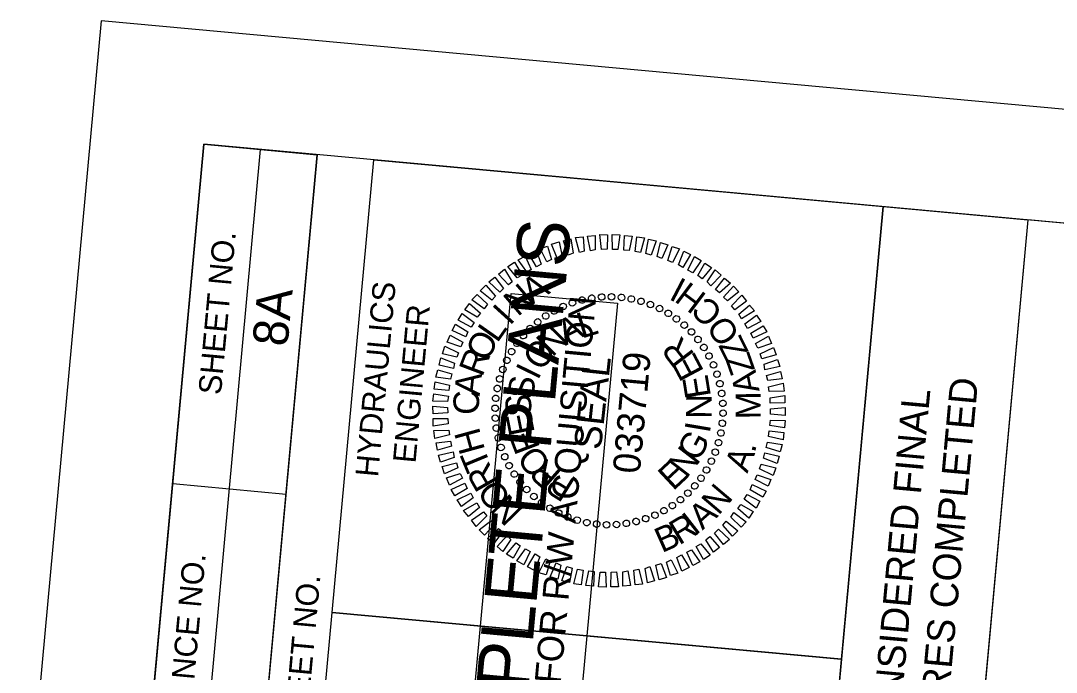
# Model space of a CAD drawing. Extents: x 2012234 to 2013485, y 445892 to 447846.
# Drawn here: x 2012372.3 to 2012600.1, y 447702.6 to 447846 of the extents above; entities that cross this region are included whole.
import ezdxf

# ---------------------------------------------------------------- set-up
doc = ezdxf.new("R2010")
doc.units = 0
for name, color, linetype in [('Sheet Clip Boundary CELL', 7, 'Continuous'), ('Sheet Data Field CELL', 7, 'Continuous'), ('Sheet Plan And Profile CELL', 7, 'Continuous'), ('Sheet Plot Border Outside CELL', 7, 'Continuous'), ('Sheet Professional Seal CELL', 7, 'Continuous'), ('Sheet Profile Grid Minor CELL', 7, 'Continuous'), ('Sheet Sticker Exception Certification CELL', 7, 'Continuous'), ('Sheet Sticker Incomplete CELL', 7, 'Continuous')]:
    doc.layers.add(name, color=color, linetype=linetype)

msp = doc.modelspace()

# ---------------------------------------------------------------- linework, layer by layer
at = {"layer": 'Sheet Clip Boundary CELL'}
msp.add_lwpolyline([(2012286.31, 446445.78), (2012511.43, 446429.21), (2012750.66, 446410.08), (2013333.05, 446362.08), (2013458.14, 447722.64), (2012593.82, 447802.11), (2012575.5, 447602.9), (2012460.65, 447613.46), (2012442.34, 447414.28), (2012375.93, 447420.39)], close=True, dxfattribs=at)
at = {"layer": 'Sheet Plan And Profile CELL'}
for p, q in [((2012406.74, 447618.42), (2012425.05, 447817.63)), ((2012419.18, 447617.27), (2012437.5, 447816.48)), ((2012405.74, 447744.09), (2012430.63, 447741.8)), ((2012440.79, 447715.76), (2012552.77, 447705.46))]:
    msp.add_line(p, q, dxfattribs=at)
for points in [[(2012412.56, 447818.78), (2012275.22, 446325.08), (2013320.81, 446228.94), (2013458.14, 447722.64)], [(2012394.24, 447619.57), (2012412.56, 447818.78), (2012437.5, 447816.48), (2012419.18, 447617.27)], [(2012440.79, 447715.76), (2012449.95, 447815.34), (2012561.97, 447805.04), (2012552.82, 447705.46)], [(2012431.63, 447616.13), (2012440.79, 447715.76), (2012552.82, 447705.46), (2012543.66, 447605.83)]]:
    msp.add_lwpolyline(points, close=True, dxfattribs=at)
at = {"layer": 'Sheet Plot Border Outside CELL'}
msp.add_lwpolyline([(2013329.68, 446052.39), (2013485.33, 447745.24), (2012389.95, 447845.96), (2012234.3, 446153.1)], close=True, dxfattribs=at)
at = {"layer": 'Sheet Professional Seal CELL'}
for p, q in [((2012491.6, 447783.09), (2012491.6, 447783.09)), ((2012493.64, 447783.91), (2012493.64, 447783.91)), ((2012495.7, 447784.53), (2012495.7, 447784.53)), ((2012497.85, 447784.93), (2012497.85, 447784.93)), ((2012500.08, 447785.13), (2012500.08, 447785.13)), ((2012502.24, 447785.23), (2012502.24, 447785.23)), ((2012504.44, 447785.08), (2012504.44, 447785.08)), ((2012506.62, 447784.73), (2012506.62, 447784.73)), ((2012508.73, 447784.18), (2012508.73, 447784.18)), ((2012510.78, 447783.54), (2012510.78, 447783.54)), ((2012487.75, 447781.04), (2012487.75, 447781.04)), ((2012489.61, 447782.12), (2012489.61, 447782.12)), ((2012512.8, 447782.65), (2012512.8, 447782.65)), ((2012514.71, 447781.57), (2012514.71, 447781.57)), ((2012485.97, 447779.7), (2012485.97, 447779.7)), ((2012516.56, 447780.4), (2012516.56, 447780.4)), ((2012518.24, 447778.99), (2012518.24, 447778.99)), ((2012482.83, 447776.67), (2012482.83, 447776.67)), ((2012484.33, 447778.29), (2012484.33, 447778.29)), ((2012519.86, 447777.48), (2012519.86, 447777.48)), ((2012481.42, 447774.99), (2012481.42, 447774.99)), ((2012521.27, 447775.85), (2012521.27, 447775.85)), ((2012522.61, 447774.07), (2012522.61, 447774.07)), ((2012480.25, 447773.14), (2012480.25, 447773.14)), ((2012523.69, 447772.21), (2012523.69, 447772.21)), ((2012479.17, 447771.23), (2012479.17, 447771.23)), ((2012524.66, 447770.21), (2012524.66, 447770.21)), ((2012477.64, 447767.16), (2012477.64, 447767.16)), ((2012478.28, 447769.21), (2012478.28, 447769.21)), ((2012525.48, 447768.18), (2012525.48, 447768.18)), ((2012477.09, 447765.05), (2012477.09, 447765.05)), ((2012526.09, 447766.12), (2012526.09, 447766.12)), ((2012476.74, 447762.87), (2012476.74, 447762.87)), ((2012526.5, 447763.97), (2012526.5, 447763.97)), ((2012476.59, 447760.68), (2012476.59, 447760.68)), ((2012526.7, 447761.74), (2012526.7, 447761.74)), ((2012476.69, 447758.51), (2012476.69, 447758.51)), ((2012501.69, 447760.12), (2012501.69, 447760.12)), ((2012526.8, 447759.57), (2012526.8, 447759.57)), ((2012476.89, 447756.28), (2012476.89, 447756.28)), ((2012526.65, 447757.38), (2012526.65, 447757.38)), ((2012477.29, 447754.13), (2012477.29, 447754.13)), ((2012526.3, 447755.2), (2012526.3, 447755.2)), ((2012477.91, 447752.07), (2012477.91, 447752.07)), ((2012525.75, 447753.09), (2012525.75, 447753.09)), ((2012478.72, 447750.04), (2012478.72, 447750.04)), ((2012524.22, 447749.02), (2012524.22, 447749.02)), ((2012525.11, 447751.04), (2012525.11, 447751.04)), ((2012479.69, 447748.04), (2012479.69, 447748.04)), ((2012523.14, 447747.11), (2012523.14, 447747.11)), ((2012480.78, 447746.18), (2012480.78, 447746.18)), ((2012482.12, 447744.4), (2012482.12, 447744.4)), ((2012521.97, 447745.26), (2012521.97, 447745.26)), ((2012483.53, 447742.76), (2012483.53, 447742.76)), ((2012520.56, 447743.58), (2012520.56, 447743.58)), ((2012485.15, 447741.26), (2012485.15, 447741.26)), ((2012486.82, 447739.85), (2012486.82, 447739.85)), ((2012517.42, 447740.55), (2012517.42, 447740.55)), ((2012519.05, 447741.96), (2012519.05, 447741.96)), ((2012488.68, 447738.68), (2012488.68, 447738.68)), ((2012490.58, 447737.6), (2012490.58, 447737.6)), ((2012513.78, 447738.13), (2012513.78, 447738.13)), ((2012515.64, 447739.21), (2012515.64, 447739.21)), ((2012492.61, 447736.71), (2012492.61, 447736.71)), ((2012494.66, 447736.07), (2012494.66, 447736.07)), ((2012496.77, 447735.52), (2012496.77, 447735.52)), ((2012505.54, 447735.32), (2012505.54, 447735.32)), ((2012507.68, 447735.72), (2012507.68, 447735.72)), ((2012509.75, 447736.34), (2012509.75, 447736.34)), ((2012511.78, 447737.15), (2012511.78, 447737.15)), ((2012498.95, 447735.17), (2012498.95, 447735.17)), ((2012501.14, 447735.02), (2012501.14, 447735.02)), ((2012503.31, 447735.12), (2012503.31, 447735.12))]:
    msp.add_line(p, q, dxfattribs=at)
for points in [[(2012490.27, 447793.71), (2012489.05, 447796.79), (2012490.7, 447797.29), (2012491.41, 447794.11)], [(2012492.69, 447794.39), (2012491.68, 447797.55), (2012493.27, 447797.95), (2012493.78, 447794.79)], [(2012495.16, 447794.97), (2012494.3, 447798.26), (2012495.97, 447798.41), (2012496.23, 447795.22)], [(2012497.6, 447795.35), (2012496.94, 447798.57), (2012498.66, 447798.71), (2012498.67, 447795.55)], [(2012500.03, 447795.58), (2012499.63, 447798.88), (2012501.34, 447798.87), (2012501.25, 447795.66)], [(2012502.45, 447795.65), (2012502.35, 447798.93), (2012504.05, 447798.87), (2012503.65, 447795.64)], [(2012504.94, 447795.48), (2012505.09, 447798.73), (2012506.78, 447798.57), (2012506.14, 447795.37)], [(2012507.43, 447795.2), (2012507.83, 447798.42), (2012509.46, 447798.17), (2012508.61, 447794.99)], [(2012509.8, 447794.73), (2012510.39, 447797.89), (2012512.06, 447797.53), (2012510.97, 447794.37)], [(2012512.3, 447794.1), (2012512.98, 447797.15), (2012514.64, 447796.64), (2012513.31, 447793.6)], [(2012485.73, 447791.82), (2012484.08, 447794.63), (2012485.66, 447795.44), (2012486.79, 447792.42)], [(2012488.04, 447792.91), (2012486.55, 447795.86), (2012488.15, 447796.37), (2012489.04, 447793.42)], [(2012514.63, 447793.23), (2012515.56, 447796.26), (2012517.17, 447795.76), (2012515.64, 447792.73)], [(2012516.95, 447792.26), (2012518.13, 447795.27), (2012519.61, 447794.48), (2012517.95, 447791.62)], [(2012481.49, 447789.4), (2012479.46, 447791.89), (2012480.9, 447792.82), (2012482.55, 447790)], [(2012483.57, 447790.71), (2012481.7, 447793.34), (2012483.23, 447794.16), (2012484.57, 447791.22)], [(2012519.05, 447791.07), (2012520.48, 447794.05), (2012521.95, 447793.16), (2012520.1, 447790.47)], [(2012521.25, 447789.86), (2012522.75, 447792.58), (2012524.23, 447791.69), (2012522.14, 447789.17)], [(2012479.54, 447787.82), (2012477.39, 447790.18), (2012478.7, 447791.26), (2012480.4, 447788.49)], [(2012523.28, 447788.47), (2012525.03, 447791.12), (2012526.33, 447789.99), (2012524.1, 447787.59)], [(2012475.91, 447784.44), (2012473.34, 447786.53), (2012474.56, 447787.73), (2012476.7, 447785.32)], [(2012477.63, 447786.19), (2012475.23, 447788.47), (2012476.53, 447789.55), (2012478.46, 447787.06)], [(2012525.13, 447786.79), (2012527.07, 447789.32), (2012528.43, 447788.24), (2012526.02, 447786.06)], [(2012474.23, 447782.53), (2012471.5, 447784.54), (2012472.67, 447785.74), (2012474.93, 447783.57)], [(2012526.89, 447785.12), (2012529.07, 447787.53), (2012530.26, 447786.32), (2012527.72, 447784.34)], [(2012528.62, 447783.21), (2012530.89, 447785.56), (2012531.93, 447784.21), (2012529.34, 447782.34)], [(2012472.71, 447780.72), (2012469.99, 447782.32), (2012470.98, 447783.74), (2012473.39, 447781.61)], [(2012530.21, 447781.4), (2012532.6, 447783.39), (2012533.69, 447782.09), (2012530.82, 447780.39)], [(2012471.35, 447778.53), (2012468.53, 447780.04), (2012469.37, 447781.52), (2012472, 447779.57)], [(2012531.57, 447779.27), (2012534.16, 447781.19), (2012535.08, 447779.75), (2012532.13, 447778.26)], [(2012470.2, 447776.38), (2012467.17, 447777.81), (2012467.89, 447779.15), (2012470.65, 447777.49)], [(2012532.89, 447777.24), (2012535.6, 447778.85), (2012536.43, 447777.47), (2012533.39, 447776.09)], [(2012469.1, 447774.22), (2012466.08, 447775.25), (2012466.72, 447776.75), (2012469.54, 447775.23)], [(2012533.93, 447774.93), (2012536.79, 447776.53), (2012537.45, 447774.91), (2012534.45, 447773.93)], [(2012468.23, 447771.89), (2012465.04, 447772.68), (2012465.59, 447774.34), (2012468.58, 447772.91)], [(2012534.93, 447772.68), (2012537.87, 447774.02), (2012538.42, 447772.41), (2012535.28, 447771.55)], [(2012467.45, 447769.4), (2012464.3, 447770.14), (2012464.7, 447771.76), (2012467.71, 447770.58)], [(2012535.78, 447770.4), (2012538.78, 447771.43), (2012539.24, 447769.88), (2012535.96, 447769.12)], [(2012466.83, 447767.05), (2012463.61, 447767.54), (2012464.06, 447769.16), (2012467.14, 447768.22)], [(2012536.35, 447767.88), (2012539.44, 447768.75), (2012539.75, 447767.17), (2012536.6, 447766.81)], [(2012466.45, 447764.57), (2012463.22, 447764.87), (2012463.42, 447766.51), (2012466.61, 447765.76)], [(2012536.78, 447765.43), (2012540.01, 447766.19), (2012540.2, 447764.47), (2012536.93, 447764.37)], [(2012466.18, 447762.18), (2012462.92, 447762.23), (2012463.12, 447763.87), (2012466.34, 447763.37)], [(2012537.11, 447762.99), (2012540.36, 447763.5), (2012540.36, 447761.84), (2012537.14, 447761.79)], [(2012466.2, 447759.67), (2012462.97, 447759.42), (2012462.92, 447761.13), (2012466.16, 447760.88)], [(2012537.18, 447760.58), (2012540.42, 447760.83), (2012540.46, 447759.12), (2012537.22, 447759.37)], [(2012466.28, 447757.25), (2012463.02, 447756.75), (2012463.02, 447758.41), (2012466.24, 447758.46)], [(2012537.2, 447758.06), (2012540.46, 447758.02), (2012540.26, 447756.38), (2012537.04, 447756.87)], [(2012466.61, 447754.81), (2012463.38, 447754.06), (2012463.18, 447755.78), (2012466.46, 447755.88)], [(2012467.04, 447752.37), (2012463.94, 447751.49), (2012463.64, 447753.08), (2012466.79, 447753.44)], [(2012536.93, 447755.68), (2012540.17, 447755.38), (2012539.97, 447753.74), (2012536.77, 447754.49)], [(2012536.56, 447753.2), (2012539.77, 447752.71), (2012539.32, 447751.09), (2012536.25, 447752.03)], [(2012467.61, 447749.85), (2012464.6, 447748.82), (2012464.14, 447750.37), (2012467.43, 447751.12)], [(2012535.94, 447750.85), (2012539.08, 447750.11), (2012538.68, 447748.49), (2012535.68, 447749.67)], [(2012468.45, 447747.57), (2012465.52, 447746.23), (2012464.96, 447747.84), (2012468.11, 447748.7)], [(2012535.16, 447748.36), (2012538.35, 447747.57), (2012537.79, 447745.91), (2012534.81, 447747.34)], [(2012469.45, 447745.31), (2012466.59, 447743.72), (2012465.94, 447745.34), (2012468.94, 447746.32)], [(2012534.29, 447746.03), (2012537.31, 447745), (2012536.67, 447743.5), (2012533.85, 447745.02)], [(2012470.5, 447743.01), (2012467.79, 447741.4), (2012466.96, 447742.78), (2012470, 447744.16)], [(2012533.19, 447743.87), (2012536.22, 447742.44), (2012535.49, 447741.1), (2012532.73, 447742.76)], [(2012471.82, 447740.98), (2012469.23, 447739.06), (2012468.31, 447740.5), (2012471.25, 447741.99)], [(2012473.18, 447738.85), (2012470.78, 447736.86), (2012469.7, 447738.16), (2012472.57, 447739.86)], [(2012532.04, 447741.72), (2012534.86, 447740.2), (2012534.02, 447738.72), (2012531.39, 447740.67)], [(2012474.77, 447737.04), (2012472.49, 447734.69), (2012471.46, 447736.04), (2012474.04, 447737.91)], [(2012529.16, 447737.72), (2012531.88, 447735.71), (2012530.72, 447734.51), (2012528.46, 447736.68)], [(2012530.68, 447739.53), (2012533.39, 447737.93), (2012532.41, 447736.51), (2012530, 447738.64)], [(2012476.5, 447735.13), (2012474.32, 447732.72), (2012473.13, 447733.93), (2012475.67, 447735.91)], [(2012527.48, 447735.81), (2012530.04, 447733.72), (2012528.83, 447732.52), (2012526.69, 447734.93)], [(2012478.25, 447733.46), (2012476.31, 447730.93), (2012474.96, 447732), (2012477.37, 447734.19)], [(2012525.76, 447734.06), (2012528.16, 447731.78), (2012526.85, 447730.7), (2012524.92, 447733.18)], [(2012480.11, 447731.78), (2012478.36, 447729.13), (2012477.06, 447730.25), (2012479.28, 447732.66)], [(2012482.14, 447730.39), (2012480.63, 447727.67), (2012479.16, 447728.56), (2012481.25, 447731.07)], [(2012521.9, 447730.85), (2012523.93, 447728.36), (2012522.49, 447727.43), (2012520.84, 447730.25)], [(2012523.85, 447732.43), (2012525.99, 447730.07), (2012524.69, 447728.99), (2012522.99, 447731.76)], [(2012484.34, 447729.18), (2012482.91, 447726.2), (2012481.43, 447727.09), (2012483.29, 447729.78)], [(2012486.44, 447727.99), (2012485.26, 447724.98), (2012483.77, 447725.77), (2012485.44, 447728.63)], [(2012517.66, 447728.43), (2012519.31, 447725.62), (2012517.73, 447724.81), (2012516.6, 447727.82)], [(2012519.82, 447729.54), (2012521.69, 447726.9), (2012520.15, 447726.09), (2012518.82, 447729.03)], [(2012488.76, 447727.02), (2012487.83, 447723.99), (2012486.22, 447724.49), (2012487.75, 447727.51)], [(2012491.09, 447726.15), (2012490.41, 447723.1), (2012488.75, 447723.61), (2012490.08, 447726.65)], [(2012513.12, 447726.54), (2012514.34, 447723.46), (2012512.69, 447722.96), (2012511.98, 447726.14)], [(2012515.35, 447727.34), (2012516.84, 447724.39), (2012515.23, 447723.88), (2012514.35, 447726.83)], [(2012493.59, 447725.52), (2012493, 447722.36), (2012491.32, 447722.72), (2012492.42, 447725.88)], [(2012495.96, 447725.05), (2012495.56, 447721.83), (2012493.93, 447722.08), (2012494.77, 447725.26)], [(2012498.44, 447724.77), (2012498.29, 447721.52), (2012496.6, 447721.68), (2012497.25, 447724.88)], [(2012500.94, 447724.59), (2012501.04, 447721.32), (2012499.34, 447721.38), (2012499.73, 447724.6)], [(2012503.35, 447724.67), (2012503.75, 447721.37), (2012502.05, 447721.38), (2012502.14, 447724.58)], [(2012505.79, 447724.9), (2012506.44, 447721.68), (2012504.72, 447721.54), (2012504.71, 447724.7)], [(2012508.23, 447725.28), (2012509.08, 447721.99), (2012507.41, 447721.84), (2012507.15, 447725.03)], [(2012510.69, 447725.86), (2012511.71, 447722.7), (2012510.12, 447722.29), (2012509.6, 447725.45)]]:
    msp.add_lwpolyline(points, close=True, dxfattribs=at)
for centre, major_axis in [((2012497.88, 447784.91), (-0.109, 0.712)), ((2012500.05, 447785.15), (-0.047, 0.718)), ((2012502.24, 447785.2), (0.016, 0.72)), ((2012504.43, 447785.06), (0.078, 0.716)), ((2012506.59, 447784.72), (0.141, 0.706)), ((2012491.59, 447783.08), (-0.29, 0.659)), ((2012493.63, 447783.87), (-0.231, 0.682)), ((2012495.73, 447784.49), (-0.171, 0.699)), ((2012508.71, 447784.2), (0.202, 0.691)), ((2012510.78, 447783.5), (0.261, 0.671)), ((2012512.79, 447782.62), (0.318, 0.646)), ((2012487.76, 447780.98), (-0.4, 0.599)), ((2012489.63, 447782.11), (-0.346, 0.631)), ((2012514.71, 447781.56), (0.374, 0.616)), ((2012516.52, 447780.35), (0.426, 0.581)), ((2012484.35, 447778.24), (-0.498, 0.52)), ((2012486, 447779.68), (-0.451, 0.562)), ((2012518.23, 447778.98), (0.475, 0.541)), ((2012482.84, 447776.66), (-0.541, 0.475)), ((2012519.81, 447777.47), (0.52, 0.498)), ((2012521.25, 447775.82), (0.562, 0.451)), ((2012480.25, 447773.14), (-0.616, 0.374)), ((2012481.47, 447774.96), (-0.581, 0.426)), ((2012522.55, 447774.06), (0.599, 0.4)), ((2012479.2, 447771.22), (-0.646, 0.318)), ((2012523.68, 447772.19), (0.631, 0.346)), ((2012478.32, 447769.22), (-0.671, 0.261)), ((2012524.65, 447770.22), (0.659, 0.29)), ((2012477.62, 447767.14), (-0.691, 0.202)), ((2012525.44, 447768.18), (0.682, 0.231)), ((2012477.1, 447765.02), (-0.706, 0.141)), ((2012526.06, 447766.08), (0.699, 0.171)), ((2012476.76, 447762.86), (-0.716, 0.078)), ((2012526.48, 447763.94), (0.712, 0.109)), ((2012476.62, 447760.67), (-0.72, 0.016)), ((2012526.72, 447761.76), (0.718, 0.047)), ((2012526.77, 447759.58), (0.72, -0.016)), ((2012476.67, 447758.49), (-0.718, -0.047)), ((2012526.62, 447757.39), (0.716, -0.078)), ((2012476.91, 447756.31), (-0.712, -0.109)), ((2012526.29, 447755.23), (0.706, -0.141)), ((2012477.33, 447754.16), (-0.699, -0.171)), ((2012525.77, 447753.11), (0.691, -0.202)), ((2012477.94, 447752.06), (-0.682, -0.231)), ((2012525.07, 447751.03), (0.671, -0.261)), ((2012478.74, 447750.02), (-0.659, -0.29)), ((2012479.7, 447748.06), (-0.631, -0.346)), ((2012524.19, 447749.03), (0.646, -0.318)), ((2012480.84, 447746.19), (-0.599, -0.4)), ((2012523.13, 447747.11), (0.616, -0.374)), ((2012482.13, 447744.43), (-0.562, -0.451)), ((2012520.55, 447743.59), (0.541, -0.475)), ((2012521.92, 447745.29), (0.581, -0.426)), ((2012483.58, 447742.78), (-0.52, -0.498)), ((2012485.16, 447741.27), (-0.475, -0.541)), ((2012519.04, 447742.01), (0.498, -0.52)), ((2012486.86, 447739.9), (-0.426, -0.581)), ((2012515.63, 447739.27), (0.4, -0.599)), ((2012517.39, 447740.56), (0.451, -0.562)), ((2012488.68, 447738.68), (-0.374, -0.616)), ((2012490.6, 447737.63), (-0.318, -0.646)), ((2012492.6, 447736.75), (-0.261, -0.671)), ((2012511.79, 447737.17), (0.29, -0.659)), ((2012513.76, 447738.14), (0.346, -0.631)), ((2012494.67, 447736.05), (-0.202, -0.691)), ((2012496.8, 447735.53), (-0.141, -0.706)), ((2012498.96, 447735.19), (-0.078, -0.716)), ((2012501.14, 447735.05), (-0.016, -0.72)), ((2012503.33, 447735.1), (0.047, -0.718)), ((2012505.51, 447735.34), (0.109, -0.712)), ((2012507.65, 447735.76), (0.171, -0.699)), ((2012509.75, 447736.38), (0.231, -0.682))]:
    msp.add_ellipse(centre, major_axis=major_axis, ratio=0.999708, dxfattribs=at)
at = {"layer": 'Sheet Sticker Exception Certification CELL'}
for p, q in [((2012543.64, 447605.83), (2012561.96, 447805.04)), ((2012561.97, 447805.04), (2012593.82, 447802.11)), ((2012593.8, 447802.11), (2012575.49, 447602.9))]:
    msp.add_line(p, q, dxfattribs=at)
at = {"layer": 'Sheet Sticker Incomplete CELL'}
msp.add_lwpolyline([(2012490.08, 447637.42), (2012466.67, 447639.57), (2012480.13, 447785.95), (2012503.53, 447783.8)], close=True, dxfattribs=at)

# ---------------------------------------------------------------- texts
at = {"layer": 'Sheet Data Field CELL'}
msp.add_text('8A', height=7.75, rotation=84.7467, dxfattribs=at).set_placement((2012430.94, 447774.1))
at = {"layer": 'Sheet Plan And Profile CELL'}
for s, height, p in [('SHEET NO.', 5, (2012416.31, 447763.5)), ('HYDRAULICS', 5, (2012450.85, 447745.41)), ('ENGINEER', 5, (2012459.11, 447748.47)), ('PROJECT REFERENCE NO.', 5.0001, (2012404.93, 447640.88)), ('R/W SHEET NO.', 5.0001, (2012433.56, 447673.19))]:
    msp.add_text(s, height=height, rotation=84.7467, dxfattribs=at).set_placement(p)
at = {"layer": 'Sheet Professional Seal CELL'}
for s, height, rotation, p in [('N', 5.64, 40.5656, (2012481.59, 447780.7)), ('A', 5.64, 33.3638, (2012484.8, 447783.37)), ('I', 5.64, 47.7668, (2012479.85, 447778.7)), ('L', 5.64, 17.1475, (2012495.67, 447775.99)), ('L', 5.64, 54.9675, (2012477.09, 447774.89)), ('N', 5.64, 45.2233, (2012489.21, 447771.77)), ('A', 5.64, 26.5069, (2012492.06, 447774.37)), ('O', 5.64, 62.1678, (2012474.85, 447770.68)), ('R', 5.64, 127.2281, (2012520.66, 447772.54)), ('O', 5.64, 54.5801, (2012486.91, 447768.61)), ('R', 5.64, 69.3678, (2012473.79, 447767.41)), ('E', 5.64, 117.8707, (2012522.68, 447768.79)), ('I', 5.64, 63.9363, (2012486.03, 447766.69)), ('SEAL', 5.998, 83.7467, (2012499.89, 447751.4)), ('A', 5.64, 83.767, (2012473.21, 447763.25)), ('S', 5.64, 82.6471, (2012484.94, 447762.47)), ('E', 5.64, 99.1584, (2012524.13, 447763.33)), ('C', 5.64, 90.9665, (2012473.15, 447759.28)), ('S', 5.64, 92.0023, (2012484.66, 447758.88)), ('N', 5.64, 89.803, (2012524.28, 447758.35)), ('E', 5.64, 101.3577, (2012485.39, 447755.35)), ('H', 5.64, 105.3661, (2012474.44, 447751.53)), ('I', 5.64, 80.4479, (2012523.82, 447755.03)), ('F', 5.64, 110.7137, (2012486.59, 447752.02)), ('G', 5.64, 61.7369, (2012521.33, 447748.68)), ('O', 5.64, 129.4279, (2012489.22, 447748.47)), ('N', 5.64, 52.3806, (2012518.74, 447745.1)), ('T', 5.64, 112.5664, (2012475.79, 447748.15)), ('R', 5.64, 119.7672, (2012477.67, 447744.56)), ('R', 5.64, 138.7863, (2012491.5, 447746.5)), ('E', 5.64, 43.0235, (2012515.78, 447742.36)), ('O', 5.64, 126.9684, (2012480.44, 447740.84)), ('P', 5.64, 148.1455, (2012494.54, 447744.61)), ('N', 5.64, 134.1702, (2012483.12, 447738.28))]:
    msp.add_text(s, height=height, rotation=rotation, dxfattribs=at).set_placement(p)
at = {"layer": 'Sheet Profile Grid Minor CELL'}
for s, height, rotation, p in [('I', 5.5, 152.3393, (2012519.02, 447788.71)), ('H', 5.5, 143.0945, (2012523.39, 447785.56)), ('C', 5.5, 134.2218, (2012527.05, 447781.91)), ('O', 5.5, 123.5173, (2012530.66, 447776.82)), ('Z', 5.5, 116.3905, (2012532.5, 447773.1)), ('033719', 5.998, 84.7467, (2012508.45, 447746.13)), ('Z', 5.5, 109.2637, (2012533.87, 447769.17)), ('A', 5.5, 101.0779, (2012534.83, 447764.5)), ('M', 5.5, 90.402, (2012535.07, 447758.28)), ('.', 5.5, 77.2217, (2012533.77, 447750.72)), ('A', 5.5, 69.0359, (2012532.11, 447746.25)), ('N', 5.5, 49.6591, (2012525.78, 447736.95)), ('I', 5.5, 37.9528, (2012520.58, 447732.54)), ('A', 5.5, 41.4733, (2012522.23, 447733.75)), ('B', 5.5, 23.8996, (2012513.31, 447728.78)), ('R', 5.5, 31.0264, (2012517.11, 447730.46))]:
    msp.add_text(s, height=height, rotation=rotation, dxfattribs=at).set_placement(p)
at = {"layer": 'Sheet Sticker Exception Certification CELL'}
for s, p in [('UNLESS ALL SIGNATURES COMPLETED', (2012568.42, 447609.47)), ('DOCUMENT NOT CONSIDERED FINAL', (2012558.73, 447616.12))]:
    msp.add_text(s, height=6.124, rotation=84.7467, dxfattribs=at).set_placement(p)
at = {"layer": 'Sheet Sticker Incomplete CELL'}
for s, height, p in [('INCOMPLETE PLANS', 11.52, (2012479.24, 447647.4)), ('DO NOT USE FOR R/W ACQUISITION', 5.76, (2012486.46, 447650))]:
    msp.add_text(s, height=height, rotation=84.7467, dxfattribs=at).set_placement(p)

doc.saveas('drawing.dxf')
